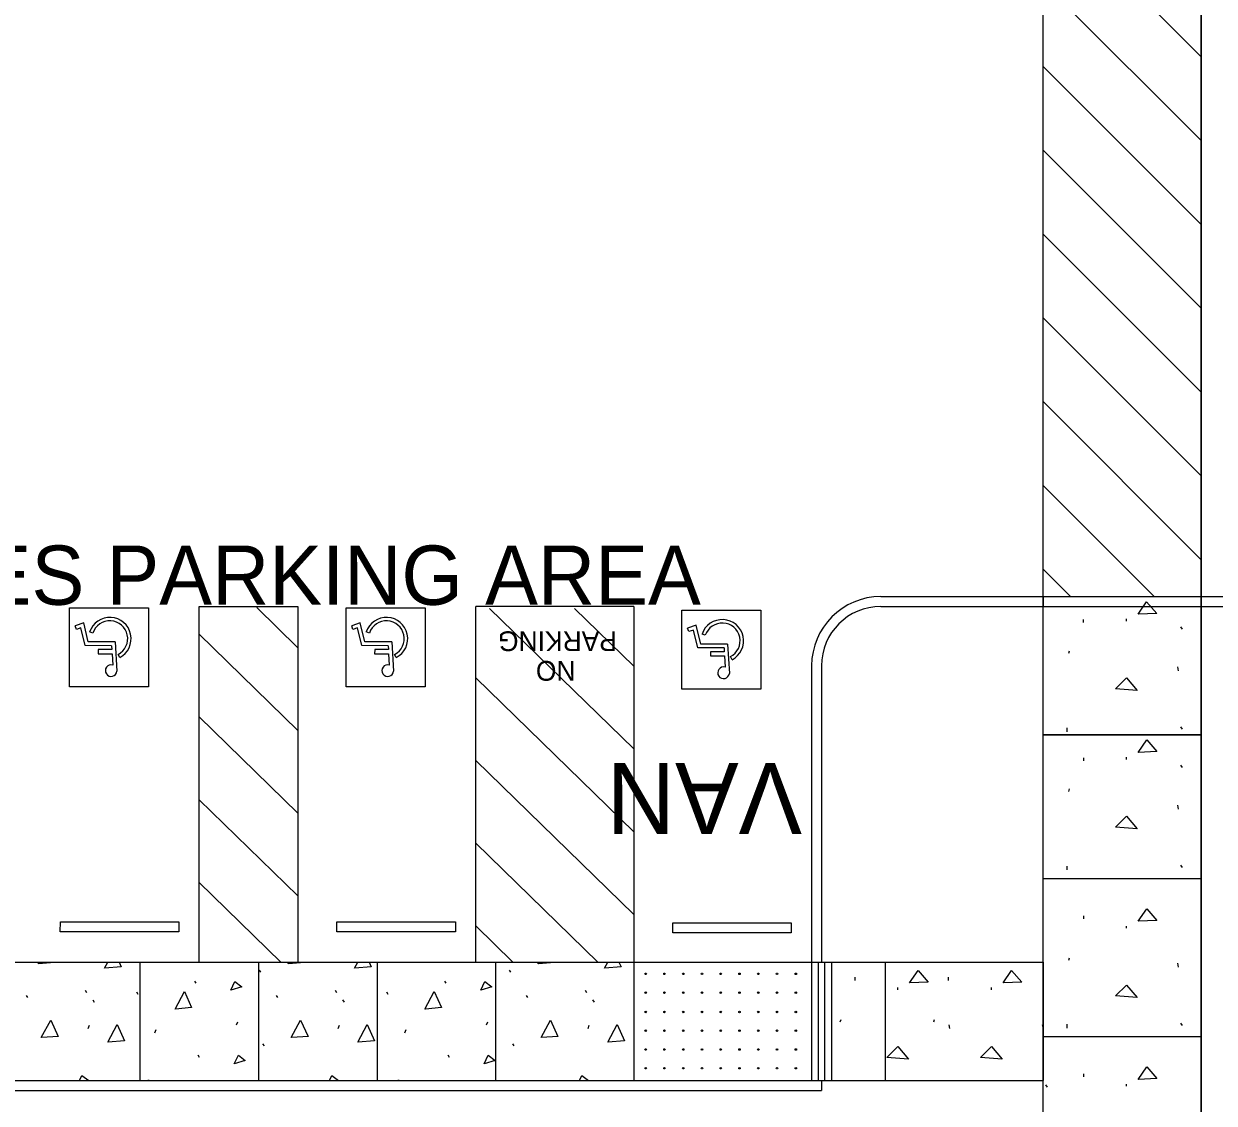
# Model space of a CAD drawing. Extents: x 6712138 to 6712574, y 1869536 to 1870160.
# Drawn here: x 6712419.5 to 6712479.7, y 1869864.9 to 1869919.6 of the extents above; entities that cross this region are included whole.
import ezdxf

# ---------------------------------------------------------------- set-up
doc = ezdxf.new("R2010")
doc.units = 0
for name, color, linetype in [('A-ANNO-TEXT', 7, 'Continuous'), ('A-COLS', 7, 'Continuous'), ('A-FLOR-CASE', 7, 'Continuous'), ('A-FLOR-PATT', 7, 'Continuous'), ('C-PRKG-CONC', 7, 'Continuous'), ('C-PRKG-STRP', 7, 'Continuous'), ('E-EQPM', 7, 'Continuous'), ('L-SITE-PAVE', 7, 'Continuous')]:
    doc.layers.add(name, color=color, linetype=linetype)

# ---------------------------------------------------------------- blocks, each defined once
blk = doc.blocks.new('G-handy2')
for p, q in [((0, 0), (-0.0002239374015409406, 0.0035868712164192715)), ((-0.000552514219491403, 0.001912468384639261), (-0.0003555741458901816, 0.001537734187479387)), ((0.000380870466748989, 0.0014482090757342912), (0.0002942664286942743, 0.002835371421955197)), ((0, 0), (0.0033054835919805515, 8.016511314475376e-07)), ((0.0020983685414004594, 0.0014486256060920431), (0.000380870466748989, 0.0014482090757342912)), ((0.0004123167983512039, 0.0009445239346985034), (0.0020984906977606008, 0.0009449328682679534)), ((0.0004419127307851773, 0.0004704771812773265), (0.0004123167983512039, 0.0009445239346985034)), ((0.0004419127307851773, 0.0004704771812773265), (0.0036734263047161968, 0.00047126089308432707)), ((0.0020984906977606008, 0.0009449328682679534), (0.0020983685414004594, 0.0014486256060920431)), ((0.0033054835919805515, 8.016511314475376e-07), (0.0038831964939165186, -0.0023286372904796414)), ((0.0036734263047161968, 0.00047126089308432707), (0.004214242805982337, -0.0017094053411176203)), ((0.002744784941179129, -0.0010810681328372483), (0.00314717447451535, -0.0012125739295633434)), ((0.0038831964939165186, -0.0023286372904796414), (0.004932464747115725, -0.0019506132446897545)), ((0.004214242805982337, -0.0017094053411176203), (0.004773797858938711, -0.0015078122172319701)), ((0.004773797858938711, -0.0015078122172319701), (0.004932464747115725, -0.0019506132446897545))]:
    blk.add_line(p, q)
for centre, radius, start, end in [((0.000485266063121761, 0.0035214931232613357), 0.0007122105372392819, 254.44408755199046, 174.7330607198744), ((0.0006632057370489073, -0.0004007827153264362), 0.0026132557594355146, 117.72399317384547, 341.90197805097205), ((0.0006632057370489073, -0.0004007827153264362), 0.002189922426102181, 117.72399317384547, 341.90197805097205)]:
    blk.add_arc(centre, radius, start, end)

msp = doc.modelspace()

# ---------------------------------------------------------------- linework, layer by layer
msp.add_line((6712471.05596572, 1869693.073490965), (6712471.055000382, 1869890.5924461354))
at = {"layer": 'A-FLOR-CASE'}
msp.add_lwpolyline([(6712471.057142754, 1869725.5729389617), (6712471.057134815, 1870137.8457074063), (6712479.057134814, 1870137.8457077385), (6712479.057145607, 1869725.5729389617)], close=True, dxfattribs=at)
at = {"layer": 'A-FLOR-PATT'}
for p, q in [((6712473.109445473, 1869889.2746593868), (6712473.109445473, 1869889.4346593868)), ((6712475.279445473, 1869889.354428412), (6712475.279445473, 1869889.464428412)), ((6712478.109445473, 1869888.939056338), (6712478.029445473, 1869889.0590563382)), ((6712472.359445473, 1869887.734428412), (6712472.399445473, 1869887.854428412)), ((6712477.909445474, 1869886.834659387), (6712477.869445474, 1869887.0346593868)), ((6712472.279445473, 1869883.7546593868), (6712472.279445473, 1869883.9546593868)), ((6712478.109445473, 1869883.8746593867), (6712478.029445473, 1869883.9946593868)), ((6712473.111584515, 1869882.274659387), (6712473.111584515, 1869882.434659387)), ((6712475.281584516, 1869882.3544284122), (6712475.281584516, 1869882.4644284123)), ((6712478.111584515, 1869881.9390563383), (6712478.031584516, 1869882.0590563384)), ((6712472.361584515, 1869880.7344284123), (6712472.401584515, 1869880.8544284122)), ((6712477.911584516, 1869879.8346593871), (6712477.871584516, 1869880.034659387)), ((6712472.281584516, 1869876.754659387), (6712472.281584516, 1869876.954659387)), ((6712478.111584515, 1869876.874659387), (6712478.031584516, 1869876.994659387)), ((6712473.111751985, 1869874.274659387), (6712473.111751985, 1869874.434659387)), ((6712475.281751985, 1869873.804659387), (6712475.281751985, 1869873.914659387)), ((6712472.361751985, 1869872.184659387), (6712472.401751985, 1869872.304659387)), ((6712431.38059823, 1869871.685944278), (6712431.447264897, 1869871.5792776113)), ((6712444.033931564, 1869871.685944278), (6712444.10059823, 1869871.5792776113)), ((6712471.057139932, 1869872.0924465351), (6712471.057140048, 1869866.0924465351)), ((6712477.911751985, 1869871.8346593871), (6712477.871751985, 1869872.034659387)), ((6712479.057139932, 1869872.0924466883), (6712479.057140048, 1869866.0924466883)), ((6712428.10059823, 1869871.1326109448), (6712428.173931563, 1869871.025944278)), ((6712440.753931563, 1869871.1326109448), (6712440.827264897, 1869871.025944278)), ((6712461.538094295, 1869871.1620919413), (6712461.538094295, 1869871.3220919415)), ((6712466.272703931, 1869871.1620919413), (6712466.272703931, 1869871.3220919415)), ((6712422.567264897, 1869870.6726109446), (6712422.64059823, 1869870.5592776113)), ((6712425.167264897, 1869870.5792776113), (6712425.240598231, 1869870.4726109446)), ((6712435.22059823, 1869870.6726109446), (6712435.293931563, 1869870.5592776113)), ((6712437.820598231, 1869870.5792776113), (6712437.893931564, 1869870.4726109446)), ((6712447.873931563, 1869870.6726109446), (6712447.947264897, 1869870.5592776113)), ((6712463.708094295, 1869870.6920919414), (6712463.708094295, 1869870.8020919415)), ((6712468.442703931, 1869870.6920919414), (6712468.442703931, 1869870.8020919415)), ((6712419.5805982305, 1869870.3992776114), (6712419.653931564, 1869870.2926109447)), ((6712422.947264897, 1869870.1726109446), (6712423.02059823, 1869870.0659442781)), ((6712432.233931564, 1869870.3992776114), (6712432.307264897, 1869870.2926109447)), ((6712435.60059823, 1869870.1726109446), (6712435.673931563, 1869870.0659442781)), ((6712444.887264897, 1869870.3992776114), (6712444.96059823, 1869870.2926109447)), ((6712448.253931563, 1869870.1726109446), (6712448.327264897, 1869870.0659442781)), ((6712422.713931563, 1869868.7326109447), (6712422.780598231, 1869868.8926109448)), ((6712426.087264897, 1869868.5126109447), (6712426.153931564, 1869868.6726109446)), ((6712430.233931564, 1869868.9126109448), (6712430.30059823, 1869869.0726109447)), ((6712435.367264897, 1869868.7326109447), (6712435.433931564, 1869868.8926109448)), ((6712438.740598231, 1869868.5126109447), (6712438.807264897, 1869868.6726109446)), ((6712442.887264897, 1869868.9126109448), (6712442.9539315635, 1869869.0726109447)), ((6712448.02059823, 1869868.7326109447), (6712448.087264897, 1869868.8926109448)), ((6712460.788094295, 1869869.0720919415), (6712460.828094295, 1869869.1920919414)), ((6712465.522703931, 1869869.0720919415), (6712465.562703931, 1869869.1920919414)), ((6712466.338094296, 1869868.7220919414), (6712466.298094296, 1869868.9220919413)), ((6712471.072703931, 1869868.7220919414), (6712471.032703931, 1869868.9220919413)), ((6712472.281751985, 1869868.754659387), (6712472.281751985, 1869868.954659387)), ((6712478.111751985, 1869868.874659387), (6712478.031751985, 1869868.994659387)), ((6712431.547264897, 1869867.945944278), (6712431.6205982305, 1869867.845944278)), ((6712444.200598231, 1869867.945944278), (6712444.273931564, 1869867.845944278)), ((6712428.267264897, 1869867.3926109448), (6712428.34059823, 1869867.2859442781)), ((6712440.92059823, 1869867.3926109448), (6712440.993931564, 1869867.2859442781)), ((6712473.111751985, 1869866.274659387), (6712473.111751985, 1869866.434659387)), ((6712471.272703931, 1869865.7620919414), (6712471.192703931, 1869865.8820919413)), ((6712475.281751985, 1869865.804659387), (6712475.281751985, 1869865.914659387))]:
    msp.add_line(p, q, dxfattribs=at)
for points in [[(6712475.869445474, 1869889.704428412), (6712476.299445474, 1869890.334428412), (6712476.809445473, 1869889.744428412)], [(6712474.7194454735, 1869885.924428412), (6712475.279445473, 1869886.474428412), (6712475.819445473, 1869885.844428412)], [(6712475.871584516, 1869882.7044284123), (6712476.301584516, 1869883.3344284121), (6712476.8115845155, 1869882.7444284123)], [(6712474.721584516, 1869878.9244284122), (6712475.281584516, 1869879.4744284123), (6712475.821584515, 1869878.8444284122)], [(6712475.871751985, 1869874.154659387), (6712476.301751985, 1869874.784659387), (6712476.811751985, 1869874.194659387)], [(6712464.298094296, 1869871.0420919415), (6712464.728094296, 1869871.6720919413), (6712465.238094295, 1869871.0820919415)], [(6712469.032703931, 1869871.0420919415), (6712469.462703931, 1869871.6720919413), (6712469.972703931, 1869871.0820919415)], [(6712474.721751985, 1869870.374659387), (6712475.281751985, 1869870.924659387), (6712475.821751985, 1869870.294659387)], [(6712463.1480942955, 1869867.2620919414), (6712463.708094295, 1869867.8120919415), (6712464.248094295, 1869867.1820919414)], [(6712467.882703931, 1869867.2620919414), (6712468.442703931, 1869867.8120919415), (6712468.982703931, 1869867.1820919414)], [(6712475.871751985, 1869866.154659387), (6712476.301751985, 1869866.784659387), (6712476.811751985, 1869866.194659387)]]:
    msp.add_lwpolyline(points, close=True, dxfattribs=at)
for points in [[(6712420.18059823, 1869871.9992776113), (6712420.229963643, 1869872.0924461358)], [(6712421.011728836, 1869872.0924461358), (6712421.02059823, 1869872.0726109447), (6712420.200598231, 1869871.9992776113)], [(6712423.547264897, 1869871.7792776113), (6712423.713197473, 1869872.0924461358)], [(6712424.282608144, 1869872.0924461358), (6712424.393931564, 1869871.845944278), (6712423.567264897, 1869871.7792776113)], [(6712432.833931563, 1869871.9992776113), (6712432.883296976, 1869872.0924461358)], [(6712433.66506217, 1869872.0924461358), (6712433.673931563, 1869872.0726109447), (6712432.853931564, 1869871.9992776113)], [(6712436.200598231, 1869871.7792776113), (6712436.366530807, 1869872.0924461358)], [(6712436.935941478, 1869872.0924461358), (6712437.047264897, 1869871.845944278), (6712436.22059823, 1869871.7792776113)], [(6712445.487264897, 1869871.9992776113), (6712445.536630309, 1869872.0924461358)], [(6712446.318395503, 1869872.0924461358), (6712446.327264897, 1869872.0726109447), (6712445.507264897, 1869871.9992776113)], [(6712448.853931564, 1869871.7792776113), (6712449.01986414, 1869872.0924461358)], [(6712449.589274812, 1869872.0924461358), (6712449.700598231, 1869871.845944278), (6712448.873931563, 1869871.7792776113)], [(6712429.94059823, 1869870.6726109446), (6712430.147264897, 1869871.1126109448), (6712430.50059823, 1869870.845944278), (6712429.94059823, 1869870.6726109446)], [(6712442.593931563, 1869870.6726109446), (6712442.80059823, 1869871.1126109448), (6712443.153931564, 1869870.845944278), (6712442.593931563, 1869870.6726109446)], [(6712427.113931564, 1869869.7126109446), (6712427.587264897, 1869870.605944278), (6712427.9539315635, 1869869.7859442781), (6712427.133931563, 1869869.7126109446)], [(6712439.767264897, 1869869.7126109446), (6712440.240598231, 1869870.605944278), (6712440.607264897, 1869869.7859442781), (6712439.787264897, 1869869.7126109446)], [(6712420.347264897, 1869868.265944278), (6712420.820598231, 1869869.1592776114), (6712421.193931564, 1869868.3326109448), (6712420.367264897, 1869868.265944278)], [(6712423.72059823, 1869868.0392776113), (6712424.193931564, 1869868.9326109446), (6712424.56059823, 1869868.1126109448), (6712423.733931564, 1869868.0392776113)], [(6712433.00059823, 1869868.265944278), (6712433.473931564, 1869869.1592776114), (6712433.847264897, 1869868.3326109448), (6712433.02059823, 1869868.265944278)], [(6712436.373931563, 1869868.0392776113), (6712436.847264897, 1869868.9326109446), (6712437.213931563, 1869868.1126109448), (6712436.387264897, 1869868.0392776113)], [(6712445.653931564, 1869868.265944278), (6712446.127264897, 1869869.1592776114), (6712446.50059823, 1869868.3326109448), (6712445.673931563, 1869868.265944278)], [(6712449.027264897, 1869868.0392776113), (6712449.50059823, 1869868.9326109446), (6712449.867264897, 1869868.1126109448), (6712449.04059823, 1869868.0392776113)], [(6712430.107264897, 1869866.9392776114), (6712430.320598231, 1869867.3726109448), (6712430.667264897, 1869867.1126109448), (6712430.107264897, 1869866.9392776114)], [(6712442.76059823, 1869866.9392776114), (6712442.973931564, 1869867.3726109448), (6712443.320598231, 1869867.1126109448), (6712442.76059823, 1869866.9392776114)], [(6712422.28153092, 1869866.092446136), (6712422.40059823, 1869866.345944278), (6712422.745095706, 1869866.092446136)], [(6712434.934864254, 1869866.092446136), (6712435.053931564, 1869866.345944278), (6712435.398429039, 1869866.092446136)], [(6712447.588197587, 1869866.092446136), (6712447.707264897, 1869866.345944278), (6712448.051762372, 1869866.092446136)], [(6712425.751530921, 1869866.092446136), (6712425.767264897, 1869866.125944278), (6712425.811649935, 1869866.092446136)], [(6712438.404864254, 1869866.092446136), (6712438.42059823, 1869866.125944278), (6712438.464983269, 1869866.092446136)]]:
    msp.add_lwpolyline(points, dxfattribs=at)
at = {"layer": 'C-PRKG-CONC'}
for p, q in [((6712462.840064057, 1869890.5924461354), (6712480.379468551, 1869890.5924461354)), ((6712471.057139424, 1869890.5924461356), (6712471.057142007, 1869890.0924461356)), ((6712479.057141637, 1869890.5924445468), (6712479.05714422, 1869890.0924445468)), ((6712428.339958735, 1869872.0924461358), (6712428.340038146, 1869890.0924461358)), ((6712428.340038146, 1869890.0924461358), (6712433.340038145, 1869890.092446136)), ((6712431.250706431, 1869890.0427208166), (6712433.340028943, 1869888.006628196)), ((6712433.340038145, 1869890.0924461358), (6712433.339958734, 1869872.0924461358)), ((6712442.339958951, 1869872.0924461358), (6712442.340038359, 1869890.0924461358)), ((6712450.340038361, 1869890.0924461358), (6712442.34003836, 1869890.0924108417)), ((6712443.041561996, 1869889.9934178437), (6712450.340006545, 1869882.8809165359)), ((6712447.340037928, 1869889.99339888), (6712450.340025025, 1869887.0698427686)), ((6712450.340038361, 1869890.0924461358), (6712450.33995895, 1869872.0924461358)), ((6712462.840064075, 1869890.0924461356), (6712480.379523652, 1869890.0924461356)), ((6712428.340031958, 1869888.6902954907), (6712433.3400104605, 1869883.817701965)), ((6712459.340064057, 1869887.0924683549), (6712459.339968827, 1869872.0924461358)), ((6712459.840064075, 1869887.0924650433), (6712459.839969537, 1869872.0924463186)), ((6712442.34002246, 1869886.4881399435), (6712450.339988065, 1869878.6919903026)), ((6712428.340013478, 1869884.5013692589), (6712433.339991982, 1869879.6287757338)), ((6712442.340003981, 1869882.2992137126), (6712450.339969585, 1869874.5030640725)), ((6712428.339994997, 1869880.3124430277), (6712433.3399735, 1869875.4398495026)), ((6712442.339985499, 1869878.110287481), (6712448.515152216, 1869872.0924461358)), ((6712428.339976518, 1869876.1235167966), (6712432.476432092, 1869872.092446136)), ((6712421.307576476, 1869873.628739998), (6712421.31080538, 1869874.1287399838)), ((6712421.31080538, 1869874.1287399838), (6712427.310930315, 1869874.1287135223)), ((6712427.310930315, 1869874.1287135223), (6712427.307701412, 1869873.6287135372)), ((6712435.307576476, 1869873.6286782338), (6712435.31080538, 1869874.1286782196)), ((6712435.31080538, 1869874.1286782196), (6712441.310930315, 1869874.1286517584)), ((6712441.310930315, 1869874.1286517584), (6712441.307701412, 1869873.628651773)), ((6712427.307701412, 1869873.6287135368), (6712421.307576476, 1869873.628739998)), ((6712441.307701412, 1869873.6286517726), (6712435.307576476, 1869873.6286782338)), ((6712442.33996702, 1869873.9213612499), (6712444.216695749, 1869872.0924461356)), ((6712452.307576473, 1869873.5793522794), (6712452.3108053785, 1869874.0793522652)), ((6712458.307701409, 1869873.5793258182), (6712452.307576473, 1869873.5793522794)), ((6712452.3108053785, 1869874.0793522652), (6712458.310930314, 1869874.079325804)), ((6712458.310930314, 1869874.079325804), (6712458.307701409, 1869873.5793258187)), ((6712377.339958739, 1869872.0924461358), (6712459.339968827, 1869872.0924461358)), ((6712377.3399322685, 1869866.0924461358), (6712459.339930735, 1869866.0924461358)), ((6712459.839931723, 1869866.0924463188), (6712459.839928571, 1869865.5924461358)), ((6712376.839930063, 1869865.592446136), (6712459.839928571, 1869865.5924461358))]:
    msp.add_line(p, q, dxfattribs=at)
for points in [[(6712421.775537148, 1869890.0194659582), (6712425.775537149, 1869890.0194659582), (6712425.775537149, 1869886.019465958), (6712421.775537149, 1869886.0194659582)], [(6712435.775537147, 1869890.0194041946), (6712439.775537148, 1869890.0194041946), (6712439.775537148, 1869886.0194041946), (6712435.775537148, 1869886.0194041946)], [(6712452.775581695, 1869889.9095653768), (6712456.775581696, 1869889.9095653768), (6712456.775581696, 1869885.9095653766), (6712452.775581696, 1869885.9095653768)]]:
    msp.add_lwpolyline(points, close=True, dxfattribs=at)
for centre, radius, end in [((6712462.840064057, 1869887.0924461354), 3.5, 179.9996362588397), ((6712462.840064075, 1869887.0924461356), 3, 179.99963889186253)]:
    msp.add_arc(centre, radius, 90, end, dxfattribs=at)
at = {"layer": 'C-PRKG-STRP'}
for p, q in [((6712471.057141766, 1869890.592445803), (6712471.057134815, 1870137.8457074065)), ((6712479.057141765, 1869890.5924461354), (6712479.057134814, 1870137.8457077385)), ((6712479.057140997, 1869917.9170369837), (6712471.867103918, 1869925.1070740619)), ((6712479.057141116, 1869913.6743961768), (6712471.05713892, 1869921.6743983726)), ((6712479.057141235, 1869909.4317553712), (6712471.057139, 1869917.431757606)), ((6712479.057141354, 1869905.1891145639), (6712471.05713908, 1869913.189116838)), ((6712479.0571414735, 1869900.9464737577), (6712471.05713916, 1869908.946476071)), ((6712479.057141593, 1869896.7038329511), (6712471.057139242, 1869904.703835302)), ((6712479.057141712, 1869892.4611921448), (6712471.057139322, 1869900.4611945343)), ((6712476.683247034, 1869890.5924461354), (6712471.057139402, 1869896.2185537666)), ((6712472.440606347, 1869890.5924461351), (6712471.057139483, 1869891.9759129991))]:
    msp.add_line(p, q, dxfattribs=at)
at = {"layer": 'E-EQPM'}
for centre in [(6712450.939878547, 1869871.4964461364), (6712451.889878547, 1869871.4964461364), (6712452.839878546, 1869871.4964461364), (6712453.789878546, 1869871.4964461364), (6712454.739878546, 1869871.4964461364), (6712455.689878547, 1869871.4964461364), (6712456.639878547, 1869871.4964461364), (6712457.589878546, 1869871.4964461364), (6712458.539878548, 1869871.4964461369), (6712450.939878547, 1869870.5464461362), (6712451.889878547, 1869870.5464461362), (6712452.839878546, 1869870.5464461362), (6712453.789878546, 1869870.5464461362), (6712454.739878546, 1869870.5464461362), (6712455.689878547, 1869870.5464461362), (6712456.639878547, 1869870.5464461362), (6712457.589878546, 1869870.5464461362), (6712458.539878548, 1869870.546446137), (6712450.939878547, 1869869.5674461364), (6712451.889878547, 1869869.5674461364), (6712452.839878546, 1869869.5674461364), (6712453.789878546, 1869869.5674461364), (6712454.739878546, 1869869.5674461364), (6712455.689878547, 1869869.5674461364), (6712456.639878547, 1869869.5674461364), (6712457.589878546, 1869869.5674461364), (6712458.539878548, 1869869.5674461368), (6712450.939878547, 1869868.6174461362), (6712451.889878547, 1869868.6174461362), (6712452.839878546, 1869868.6174461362), (6712453.789878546, 1869868.6174461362), (6712454.739878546, 1869868.6174461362), (6712455.689878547, 1869868.6174461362), (6712456.639878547, 1869868.6174461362), (6712457.589878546, 1869868.6174461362), (6712458.539878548, 1869868.617446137), (6712450.939878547, 1869867.6674461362), (6712451.889878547, 1869867.6674461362), (6712452.839878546, 1869867.6674461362), (6712453.789878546, 1869867.6674461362), (6712454.739878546, 1869867.6674461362), (6712455.689878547, 1869867.6674461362), (6712456.639878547, 1869867.6674461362), (6712457.589878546, 1869867.6674461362), (6712458.539878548, 1869867.6674461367), (6712450.939878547, 1869866.7174461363), (6712451.889878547, 1869866.7174461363), (6712452.839878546, 1869866.7174461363), (6712453.789878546, 1869866.7174461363), (6712454.739878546, 1869866.7174461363), (6712455.689878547, 1869866.7174461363), (6712456.639878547, 1869866.7174461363), (6712457.589878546, 1869866.7174461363), (6712458.539878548, 1869866.7174461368)]:
    msp.add_circle(centre, 0.0375, dxfattribs=at)
at = {"layer": 'L-SITE-PAVE'}
for p, q in [((6712471.055000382, 1869890.5924461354), (6712479.0550027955, 1869890.5924461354)), ((6712479.057145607, 1869725.5729389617), (6712479.057144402, 1869890.5924461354)), ((6712471.057139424, 1869883.6124461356), (6712479.057141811, 1869883.6124461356)), ((6712471.057139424, 1869883.5924461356), (6712479.057141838, 1869883.5924461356)), ((6712479.057144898, 1869876.3048828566), (6712471.057144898, 1869876.3048828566)), ((6712425.339958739, 1869872.0924461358), (6712425.339958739, 1869866.092446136)), ((6712431.339958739, 1869872.0924461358), (6712431.339958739, 1869866.092446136)), ((6712437.339958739, 1869872.0924461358), (6712437.339958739, 1869866.092446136)), ((6712443.339958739, 1869872.0924461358), (6712443.339958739, 1869866.092446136)), ((6712450.33995895, 1869872.0924461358), (6712471.057139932, 1869872.092446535)), ((6712450.33995895, 1869872.0924461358), (6712450.33995895, 1869866.092446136)), ((6712459.33995895, 1869872.0924461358), (6712459.33995895, 1869866.092446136)), ((6712459.66995895, 1869872.0924461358), (6712459.66995895, 1869866.092446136)), ((6712459.99995895, 1869872.0924461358), (6712459.99995895, 1869866.092446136)), ((6712460.33995895, 1869872.0924461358), (6712460.33995895, 1869866.092446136)), ((6712463.057139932, 1869872.0924463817), (6712463.057140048, 1869866.0924463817)), ((6712479.057144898, 1869868.3048828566), (6712471.057144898, 1869868.3048828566)), ((6712450.33995895, 1869866.092446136), (6712471.057140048, 1869866.0924465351))]:
    msp.add_line(p, q, dxfattribs=at)

# ---------------------------------------------------------------- block references
at = {"layer": 'C-PRKG-CONC', "xscale": 412.3229143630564, "yscale": 412.3229143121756, "rotation": 179.73949444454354}
for p in [(6712424.088809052, 1869888.2963903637), (6712438.088809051, 1869888.2963286), (6712455.088853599, 1869888.1864897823)]:
    msp.add_blockref('G-handy2', p, dxfattribs=at)

# ---------------------------------------------------------------- texts
at = {"layer": 'A-ANNO-TEXT'}
msp.add_text('BIG VEHICLES PARKING AREA', height=3, dxfattribs=at).set_placement((6712394.655976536, 1869890.1767807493))
at = {"layer": 'A-COLS'}
for s, height, rotation, p in [('PARKING', 1, 180, (6712449.484855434, 1869888.8336792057)), ('NO', 1, 180, (6712447.388056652, 1869887.3336792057)), ('VAN', 3.6000000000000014, 179.99999232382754, (6712458.853364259, 1869882.1724093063))]:
    msp.add_text(s, height=height, rotation=rotation, dxfattribs=at).set_placement(p)

doc.saveas('drawing.dxf')
